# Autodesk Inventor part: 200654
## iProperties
Created: 2007-10
Part Number: 200654
Document SubType Name: Modeling
Designer: TH
Density: 7.85 g/cm^3
Mass: 777.491 g
Surface Area: 2126.93 cm^2
Volume: 99.0434 cm^3
Material: Steel
Description: FRONT TOP SHEILD
Component Category: Lower Component
Author: TH
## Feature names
1. Extrusion1
2. Extrusion2
3. Chamfer1
4. Mirror1
5. Extrusion3
6. Chamfer2
7. Chamfer3
8. Fillet3
9. Fillet8
10. Fillet9
11. Fillet10
12. Fillet13
13. Fillet14
14. Shell1
15. Extrusion4
16. Extrusion5
17. Fillet11
18. Fillet12
19. Mirror2
20. Extrusion7
21. Extrusion8
22. Extrusion9
23. Mirror4
24. Fillet15
25. Fillet16
26. Extrusion11
27. Fillet17
28. Extrusion12
29. Extrusion13
30. Extrusion17
31. Fillet18
32. Extrusion14
33. Fillet19
34. Extrusion15
35. Extrusion16
36. Rectangular Pattern1
37. Fillet20
38. Fillet21
39. Extrusion18
40. Fillet22
